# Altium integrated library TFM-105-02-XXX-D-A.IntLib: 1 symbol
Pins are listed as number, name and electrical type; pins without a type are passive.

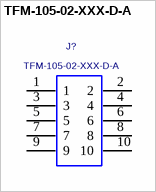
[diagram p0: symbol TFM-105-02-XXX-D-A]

## TFM-105-02-XXX-D-A
designator J?
0.050" TERMINAL STRIP, SURFACE MOUNT ASSEMBLY.; MANUFACTURER: SAMTEC
footprint TFM-105-02-XXX-D-A
pins: 1, 2, 3, 4, 5, 6, 7, 8, 9, 10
